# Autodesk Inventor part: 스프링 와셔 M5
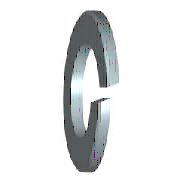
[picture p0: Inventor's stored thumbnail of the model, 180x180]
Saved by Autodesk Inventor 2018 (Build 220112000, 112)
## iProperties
IsCustomPart: 1
Created: 2012-02
Part Number: 스프링 와셔 M5
Material: 강철, 연강
Description: 스프링 와셔
Document SubType Name: Modeling
Standard: JIS B 1251
Designer: mdu-01
Standards Organization: JIS
Language: ko-KR
Size Designation: 번호 2 5
Categories: <MemberInstance><Categories><Category DisplayName="조임쇠" InternalName="e4da775c-781d-43d5-af7c-5136215cf5a6" Mnemonic="FSTN"><Category DisplayName="와셔" InternalN
Density: 1 g/cm^3
Appearance: 강철
Author: mdu-01
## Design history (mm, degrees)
sketch "스케치1"
  geometry: C1 r 4.6 at (0, 0); C2 r 2.55 at (0, 0); 1 further point
  constraints: 2 centre point, 2 coincident
  dimensions: "d0" = 5.1 diameter of C2 (= SD1); "d1" = 9.2 diameter of C1 (= SD2)
extrude "본체" new body sketch "스케치1" distance "d2" = 1.3 (= SD); taper "d3" = 0 deg
sketch "스케치2"
  geometry: L1 (0, -2.55)-(0, 2.55) reference; L2 (1.3, 4.6)-(1.3, -4.6) reference; L3 (-1.2, 0)-(7.2, 0) reference; L4 (0, -0.26)-(1.3, 0.213); L5 (0, 0.26)-(1.3, 0.733)
  constraints: 4 end point, 4 point on line, 1 parallel
  dimensions: "d4" = 0.26 distance from line of L3 L4.start (= 0.2 x SD); "d5" = 0.26 distance from line of L3 L5.start (= 0.2 x SD); "d6" = 70 deg angle of L2 L4 (= FAWI)
extrude "절단부" cut sketch "스케치2" stored distance "d7" = 1.3 (= SD); taper "d8" = 0 deg
workaxis "Work Axis1"
workplane "Work Plane1"
body "Solid1"
other parameters: "SD1" = 5.1 [user parameter; used in 1 equation term], "SD2" = 9.2 [user parameter; used in 1 equation term], "SD" = 1.3 [user parameter; used in 4 equation terms], "FAWI" = 70 deg [user parameter; used in 1 equation term], "d9" = 0, "d10" = 0, "d11" = 0, "d12" = 0, "SDI" = 1.7 [user parameter], "NND" = 5 [user parameter]
